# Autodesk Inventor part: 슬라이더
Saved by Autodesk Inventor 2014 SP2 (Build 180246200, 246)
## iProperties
Created: 2025-07
Part Number: 슬라이더
Material: Generic
Document SubType Name: Modeling
Designer: Administrator
Density: 1 g/cm^3
Appearance: Default
Author: Administrator
Author: jhkim
Creation Date: 2025-06-11
Sending System: Autodesk Inventor 2026
Preprocessor: ST-DEVELOPER v20.1
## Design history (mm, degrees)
node "슬라이더1"
node "솔리드1"
node "기준1"
